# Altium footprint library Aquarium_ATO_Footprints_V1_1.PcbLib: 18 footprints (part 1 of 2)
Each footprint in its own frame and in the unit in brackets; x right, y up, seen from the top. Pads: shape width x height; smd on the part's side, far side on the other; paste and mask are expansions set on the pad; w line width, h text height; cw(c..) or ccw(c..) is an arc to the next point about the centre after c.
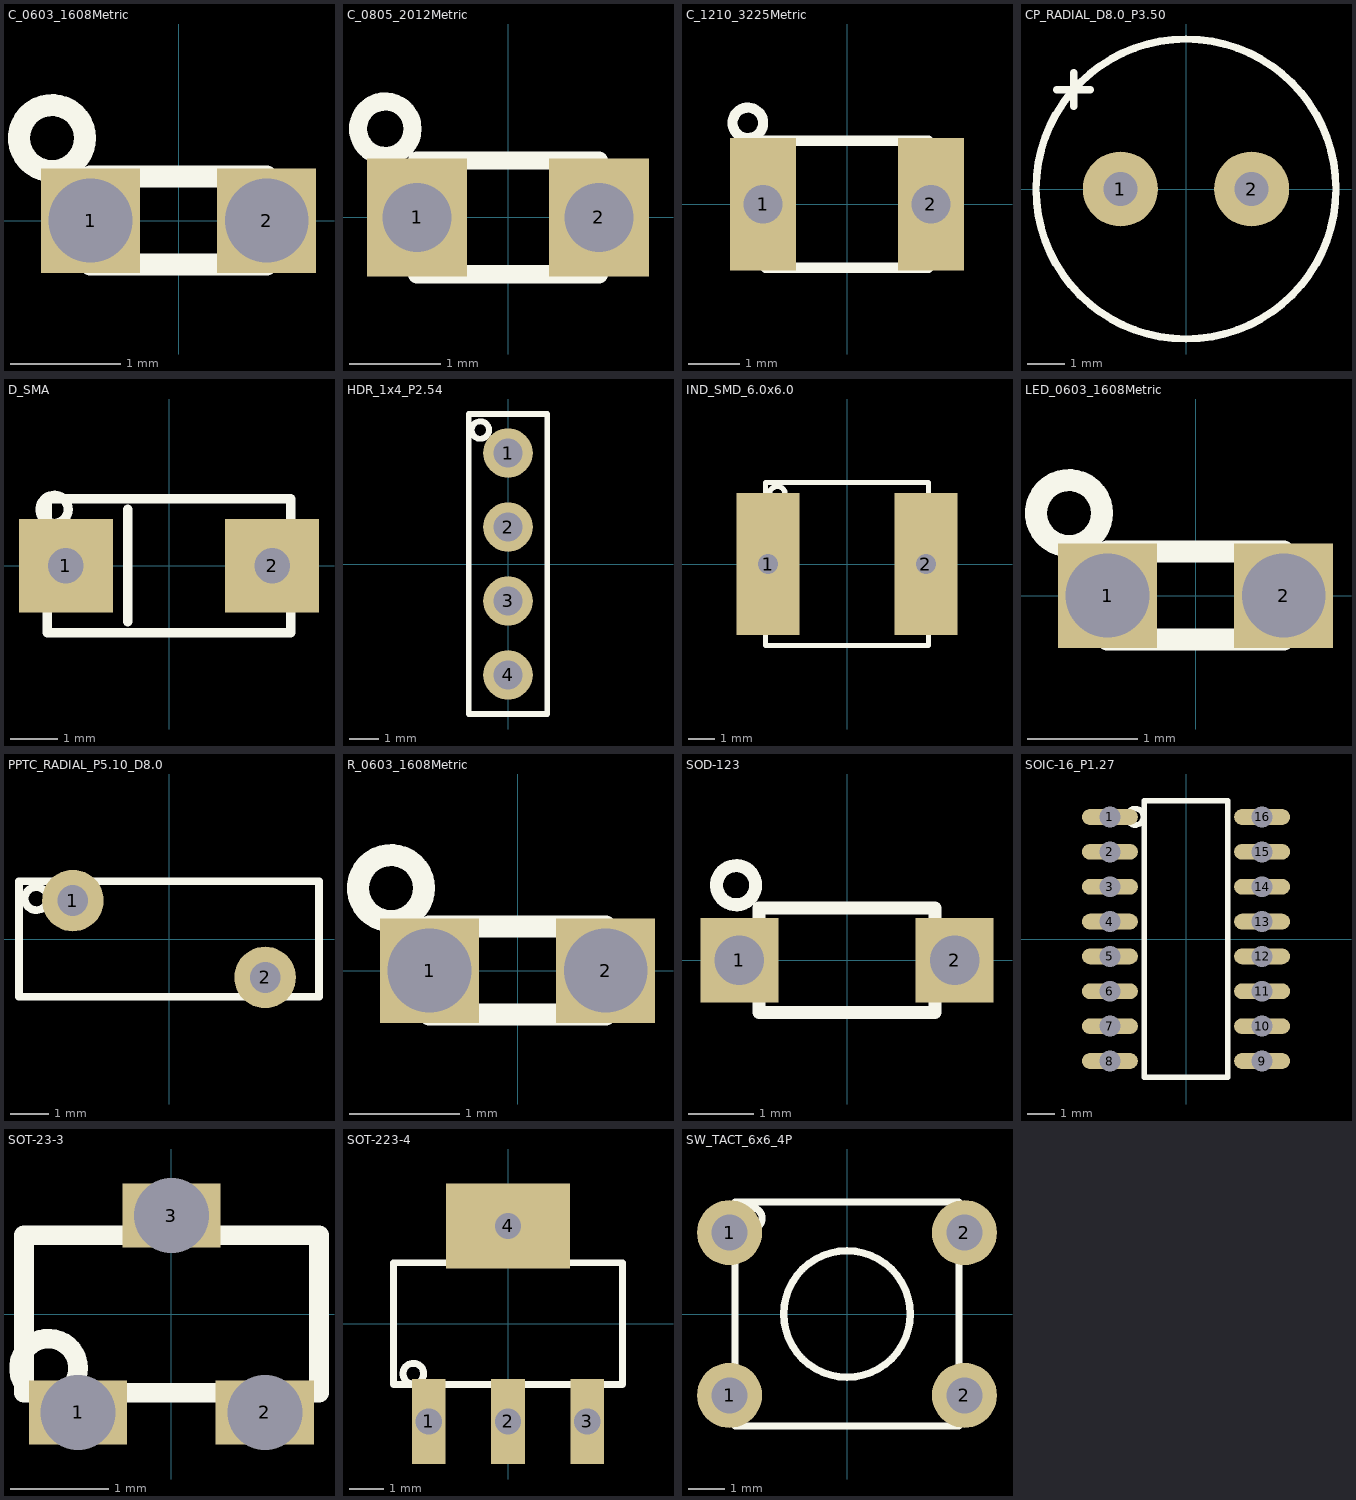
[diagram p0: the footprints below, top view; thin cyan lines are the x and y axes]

## C_0603_1608Metric [mm]
pads (2):
  rect 0.9x0.95 smd: 1(-0.8,0) 2(0.8,0)
Top Overlay:
  circle w0.2: c-1.15,0.75 r0.3
  lines w0.2: -0.8,-0.4 -0.8,0.4 0.8,0.4 0.8,-0.4 -0.8,-0.4

## C_0805_2012Metric [mm]
pads (2):
  rect 1.1x1.3 smd: 1(-1,0) 2(1,0)
Top Overlay:
  circle w0.2: c-1.35,0.975 r0.3
  lines w0.2: -1,-0.625 -1,0.625 1,0.625 1,-0.625 -1,-0.625

## C_1210_3225Metric [mm]
pads (2):
  rect 1.3x2.6 smd: 1(-1.65,0) 2(1.65,0)
Top Overlay:
  circle w0.2: c-1.95,1.6 r0.3
  lines w0.2: -1.6,-1.25 -1.6,1.25 1.6,1.25 1.6,-1.25 -1.6,-1.25

## CP_RADIAL_D8.0_P3.50 [mm]
pads (2):
  round 2 hole 0.9: 1(-1.75,0) 2(1.75,0)
Top Overlay:
  circle w0.2: c0,0 r4
  lines w0.2: -3.45,2.65 -2.55,2.65 ; -3,2.2 -3,3.1

## D_SMA [mm]
pads (2):
  rect 2x2 smd: 1(-2.2,0) 2(2.2,0)
Top Overlay:
  circle w0.2: c-2.45,1.2 r0.3
  lines w0.2: -0.88,-1.2 -0.88,1.2 ; -2.6,-1.43 -2.6,1.43 2.6,1.43 2.6,-1.43 -2.6,-1.43

## HDR_1x4_P2.54 [mm]
pads (4):
  round 1.7 hole 1: 1(0,3.81) 2(0,1.27) 3(0,-1.27) 4(0,-3.81)
Top Overlay:
  circle w0.2: c-0.95,4.6 r0.3
  lines w0.2: -1.35,-5.15 -1.35,5.15 1.35,5.15 1.35,-5.15 -1.35,-5.15

## IND_SMD_6.0x6.0 [mm]
pads (2):
  rect 2.4x5.4 smd: 1(-3,0) 2(3,0)
Top Overlay:
  circle w0.2: c-2.65,2.65 r0.3
  lines w0.2: -3.1,-3.1 -3.1,3.1 3.1,3.1 3.1,-3.1 -3.1,-3.1

## LED_0603_1608Metric [mm]
pads (2):
  rect 0.9x0.95 smd: 1(-0.8,0) 2(0.8,0)
Top Overlay:
  circle w0.2: c-1.15,0.75 r0.3
  lines w0.2: -0.8,-0.4 -0.8,0.4 0.8,0.4 0.8,-0.4 -0.8,-0.4

## PPTC_RADIAL_P5.10_D8.0 [mm]
pads (2):
  round 1.6 hole 0.8: 1(-2.5,1) 2(2.5,-1)
Top Overlay:
  circle w0.2: c-3.45,1.05 r0.3
  lines w0.2: -3.9,-1.5 -3.9,1.5 3.9,1.5 3.9,-1.5 -3.9,-1.5

## R_0603_1608Metric [mm]
pads (2):
  rect 0.9x0.95 smd: 1(-0.8,0) 2(0.8,0)
Top Overlay:
  circle w0.2: c-1.15,0.75 r0.3
  lines w0.2: -0.8,-0.4 -0.8,0.4 0.8,0.4 0.8,-0.4 -0.8,-0.4

## SOD-123 [mm]
pads (2):
  rect 1.2x1.3 smd: 1(-1.65,0) 2(1.65,0)
Top Overlay:
  circle w0.2: c-1.7,1.15 r0.3
  lines w0.2: -1.35,-0.8 -1.35,0.8 1.35,0.8 1.35,-0.8 -1.35,-0.8

## SOIC-16_P1.27 [mm]
pads (16):
  oval 2.04x0.57 smd: 1(-2.77,4.445) 2(-2.77,3.175) 3(-2.77,1.905) 4(-2.77,0.635) 5(-2.77,-0.635) 6(-2.77,-1.905) 7(-2.77,-3.175) 8(-2.77,-4.445) 9(2.77,-4.445) 10(2.77,-3.175) 11(2.77,-1.905) 12(2.77,-0.635) 13(2.77,0.635) 14(2.77,1.905) 15(2.77,3.175) 16(2.77,4.445)
Top Overlay:
  circle w0.2: c-1.85,4.45 r0.3
  lines w0.2: -1.52,-5.03 -1.52,5.03 1.52,5.03 1.52,-5.03 -1.52,-5.03

## SOT-23-3 [mm]
pads (3):
  rect 1x0.65 smd: 1(-0.95,-1) 2(0.95,-1) 3(0,1)
Top Overlay:
  circle w0.2: c-1.25,-0.55 r0.3
  lines w0.2: -1.5,-0.8 -1.5,0.8 1.5,0.8 1.5,-0.8 -1.5,-0.8

## SOT-223-4 [mm]
pads (4):
  rect 0.98x2.47 smd: 1(-2.3,-2.84) 2(0,-2.84) 3(2.3,-2.84)
  rect 3.6x2.47 smd: 4(0,2.84)
Top Overlay:
  circle w0.2: c-2.75,-1.45 r0.3
  lines w0.2: -3.33,-1.77 -3.33,1.77 3.33,1.77 3.33,-1.77 -3.33,-1.77

## SW_TACT_6x6_4P [mm]
pads (4):
  round 1.8 hole 1: 1(-3.25,-2.25) 1(-3.25,2.25) 2(3.25,-2.25) 2(3.25,2.25)
Top Overlay:
  circle w0.2: c-2.65,2.65 r0.3
  circle w0.2: c0,0 r1.75
  lines w0.2: -3.1,-3.1 -3.1,3.1 3.1,3.1 3.1,-3.1 -3.1,-3.1

## TB_2P_P5.08 [mm]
